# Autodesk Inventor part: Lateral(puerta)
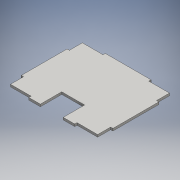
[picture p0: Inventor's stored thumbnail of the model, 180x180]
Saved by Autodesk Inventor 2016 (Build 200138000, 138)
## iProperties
Created: 2016-06
Part Number: Lateral(puerta)
Material: Genérico
Document SubType Name: Modeling
Designer: adm
Density: 1 g/cm^3
Appearance: Valor por defecto
Author: adm
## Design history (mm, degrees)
sketch "Boceto1"
  geometry: L1 (1.5, 50)-(30, 50); L2 (30, 50)-(30, 47); L3 (57, -47)-(57, -30); L4 (30, -47)-(57, -47); L5 (57, -30)-(60, -30); L6 (60, 30)-(60, -30); L7 (57, 30)-(60, 30); L8 (57, 47)-(30, 47); L9 (57, 30)-(57, 47); L10 (42, 27)-(45, 27); L11 (45, 27)-(45, 37); L12 (45, 37)-(42, 37); L13 (42, 37)-(42, 27); L14 (45, 27)-(42, 37); L15 (42, 27)-(45, 37); L16 (-45, 27)-(-45, 37); L17 (-42, 37)-(-42, 27); L18 (-42, 27)-(-45, 37); L19 (-45, 27)-(-42, 37); L20 (-45, 37)-(-42, 37); L21 (-57, 30)-(-57, 47); L22 (-57, 47)-(-30, 47); L23 (-30, 50)-(-30, 47); L24 (1.5, 50)-(-30, 50); L25 (30, -47)-(30, -50); L26 (-42, 27)-(-45, 27); L27 (-57, 30)-(-60, 30); L28 (-60, 30)-(-60, -30); L29 (1.5, -22)-(15, -22); L30 (1.5, -22)-(-15, -22); L31 (30, -50)-(15, -50); L32 (15, -50)-(15, -22); L33 (-15, -50)-(-15, -22); L34 (-30, -50)-(-15, -50); L35 (-30, -47)-(-30, -50); L36 (-57, -30)-(-60, -30); L37 (-57, -47)-(-57, -30); L38 (-30, -47)-(-57, -47); 3 further points
  constraints: 76 end point, 4 midpoint, 4 parallel, 4 perpendicular, 2 horizontal
  dimensions: "d0" = 94 distance of L3.start L8.start; "d1" = 3 distance of L12.end L11.end; "d2" = 100 distance between parallel lines of L31 L1; "d5" = 28 distance between parallel lines of L29 L31; "d8" = 120 distance between parallel lines of L6 L28; "d9" = 30 distance between parallel lines of L23 L28; "d10" = 30 distance between parallel lines of L2 L6; "d11" = 3 distance between parallel lines of L6 L3; "d13" = 3 distance between parallel lines of L6 L9; "d14" = 30 distance between parallel lines of L32 L33; "d15" = 15 distance of L25.end L31.end; "d16" = 15 distance between parallel lines of L25 L32; "d17" = 60 distance between parallel lines of L2 L23 (derived)
extrude "Extrusión1" new body sketch "Boceto1" distance "d3" = 3; taper "d4" = 0 deg
sketch "Boceto2"
  geometry: L1 (-45, 37)-(-42, 37) reference; L2 (-42, 37)-(-42, 27) reference; L3 (-45, 37)-(-42, 37); L4 (-42, 37)-(-42, 27); L5 (-42, 27)-(-45, 27); L6 (-45, 27)-(-45, 37); L7 (45, 37)-(42, 37) reference; L8 (45, 27)-(45, 37) reference; L9 (42, 37)-(45, 37); L10 (45, 37)-(45, 27); L11 (45, 27)-(42, 27); L12 (42, 27)-(42, 37); 1 further point
  constraints: 16 end point, 4 parallel, 2 horizontal, 2 perpendicular
extrude "Extrusión2" join sketch "Boceto2" distance "d6" = 3; taper "d7" = 0 deg
node "Sólido1"
